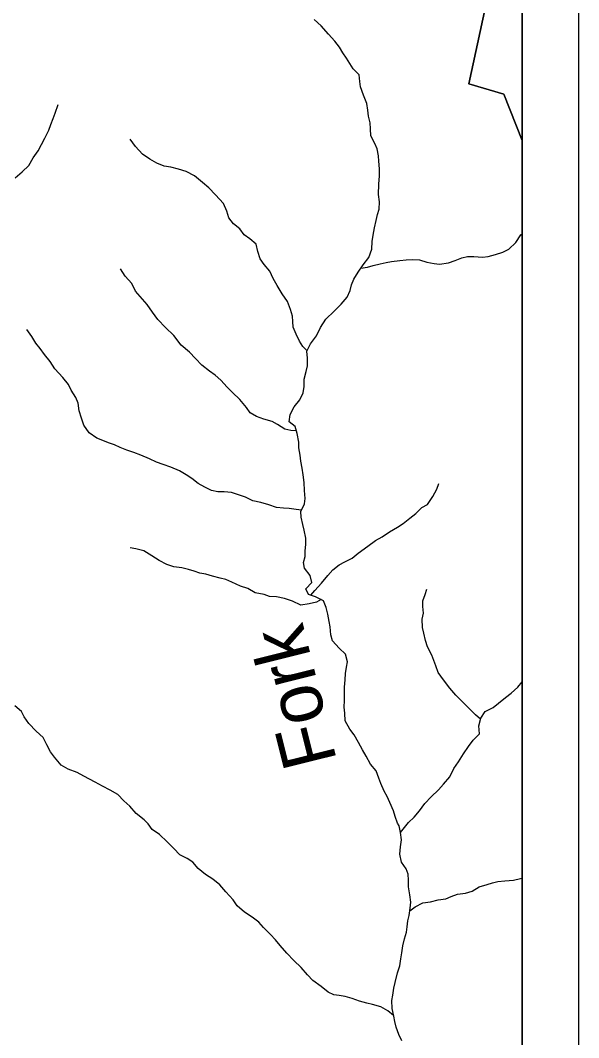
# Model space of a CAD drawing. Extents: x 0 to 34, y 0 to 22.
# Drawn here: x 8.014 to 9, y 17.355 to 19.152 of the extents above; entities that cross this region are included whole.
import ezdxf

# ---------------------------------------------------------------- set-up
doc = ezdxf.new("R2010")
doc.units = 0
for name, color, linetype in [('Default', 7, 'Continuous'), ('GM_X_Minor_River', 7, 'Continuous'), ('GM_X_Minor_River_Text', 7, 'Continuous'), ('SH_Cut_Line', 7, 'Continuous'), ('SH_Data', 7, 'Continuous')]:
    doc.layers.add(name, color=color, linetype=linetype)

msp = doc.modelspace()

# ---------------------------------------------------------------- linework, layer by layer
at = {"layer": 'Default'}
for points in [[(8.8461, 19.2253), (8.806, 19.0402), (8.8678, 19.0216), (8.9, 18.9397), (8.9, 20.9)], [(8.9, 14.1), (8.9, 18.9397), (8.8678, 19.0216), (8.806, 19.0402), (8.8461, 19.2253)]]:
    msp.add_lwpolyline(points, dxfattribs=at)
at = {"layer": 'GM_X_Minor_River'}
for points in [[(8.6401, 18.9346), (8.633, 18.948), (8.6327, 18.9605), (8.632, 18.9711), (8.6291, 18.9826), (8.6276, 18.9936), (8.6258, 19.0054), (8.6199, 19.0198), (8.6146, 19.0347), (8.6136, 19.0442), (8.6125, 19.056), (8.602, 19.0663), (8.59, 19.0854), (8.5836, 19.0949), (8.578, 19.1048), (8.5693, 19.1151), (8.5584, 19.1277), (8.5456, 19.1426), (8.5332, 19.1537)], [(8.0053, 18.8741), (8.0175, 18.8843), (8.029, 18.896), (8.0367, 18.9093), (8.0458, 18.9217), (8.0516, 18.9331), (8.0574, 18.9441), (8.0643, 18.9581), (8.0682, 18.9683), (8.0724, 18.9789), (8.0755, 18.9884), (8.0813, 19.0032)], [(8.5204, 18.5683), (8.513, 18.5761), (8.5074, 18.5856), (8.5014, 18.5978), (8.4958, 18.6104), (8.4955, 18.6199), (8.4948, 18.6294), (8.4914, 18.6416), (8.4862, 18.6553), (8.4765, 18.669), (8.4678, 18.6839), (8.4607, 18.6961), (8.4547, 18.7091), (8.4449, 18.7209), (8.4378, 18.7308), (8.4337, 18.7438), (8.4308, 18.7567), (8.4195, 18.7663), (8.4097, 18.7735), (8.4018, 18.7838), (8.3908, 18.7927), (8.3825, 18.803), (8.3788, 18.8148), (8.3729, 18.8285), (8.3586, 18.8438), (8.3473, 18.8564), (8.3356, 18.8659), (8.322, 18.8774), (8.3073, 18.8851), (8.2932, 18.889), (8.28, 18.8925), (8.2679, 18.8945), (8.255, 18.8999), (8.2426, 18.9072), (8.2297, 18.916), (8.2177, 18.9294), (8.2083, 18.9423)], [(8.6829, 17.7294), (8.6803, 17.7341), (8.6758, 17.7459), (8.6732, 17.7558), (8.6669, 17.7703), (8.662, 17.7809), (8.6568, 17.7904), (8.6508, 17.8038), (8.6471, 17.8137), (8.6422, 17.8262), (8.6324, 17.8381), (8.625, 17.8522), (8.6186, 17.8632), (8.6115, 17.8766), (8.6036, 17.8899), (8.5961, 17.8999), (8.5878, 17.9147), (8.5872, 17.928), (8.5861, 17.9387), (8.5866, 17.9504), (8.5867, 17.9744), (8.5876, 17.9873), (8.5884, 17.9983), (8.59, 18.0093), (8.5916, 18.0191), (8.5882, 18.0325), (8.5769, 18.0432), (8.5656, 18.0558), (8.5623, 18.0664), (8.5613, 18.0809), (8.5594, 18.0904), (8.5572, 18.1033), (8.5543, 18.1147), (8.5494, 18.1269), (8.5354, 18.1338), (8.5233, 18.1381), (8.5185, 18.1476), (8.5288, 18.1593), (8.5258, 18.1715), (8.5157, 18.1841), (8.5139, 18.1944), (8.5173, 18.205), (8.5174, 18.2145), (8.5182, 18.227), (8.5183, 18.2376), (8.5154, 18.2513), (8.5128, 18.2616), (8.5102, 18.2745), (8.5095, 18.2844), (8.5161, 18.2981), (8.5169, 18.3075), (8.5158, 18.3216), (8.5152, 18.336), (8.5138, 18.349), (8.5119, 18.3611), (8.5097, 18.3737), (8.5083, 18.3843), (8.5057, 18.3969), (8.5062, 18.4068), (8.5032, 18.422), (8.4992, 18.4345), (8.489, 18.4429), (8.4906, 18.4559), (8.4979, 18.4695), (8.5078, 18.4816), (8.5136, 18.4944), (8.5152, 18.5051), (8.5153, 18.518), (8.5191, 18.5316), (8.5211, 18.5419), (8.5212, 18.5552), (8.5201, 18.5677), (8.5267, 18.5806), (8.537, 18.5946), (8.5443, 18.6093), (8.5539, 18.6241), (8.5684, 18.6381), (8.5806, 18.6505), (8.5913, 18.6634), (8.5963, 18.6747), (8.599, 18.685), (8.6033, 18.6948), (8.6106, 18.7073), (8.6194, 18.7202), (8.6297, 18.733), (8.6347, 18.7482), (8.6352, 18.7615), (8.6372, 18.7725), (8.6395, 18.7854), (8.6423, 18.7986), (8.645, 18.8093), (8.6477, 18.8187), (8.6486, 18.8313), (8.6467, 18.8446), (8.6472, 18.8628), (8.6485, 18.8772), (8.6482, 18.8898), (8.6471, 18.9031), (8.6464, 18.9129), (8.6442, 18.9251), (8.6401, 18.9346)], [(8.6153, 18.7142), (8.6273, 18.7163), (8.6372, 18.7193), (8.6497, 18.7222), (8.66, 18.7241), (8.6698, 18.7263), (8.6843, 18.7277), (8.6956, 18.7288), (8.7063, 18.7299), (8.7188, 18.729), (8.732, 18.7251), (8.7449, 18.7224), (8.7544, 18.7216), (8.7703, 18.7237), (8.7821, 18.7278), (8.7935, 18.7327), (8.8038, 18.7349), (8.8148, 18.7352), (8.8303, 18.734), (8.8402, 18.7347), (8.8531, 18.7384), (8.8664, 18.7425), (8.8767, 18.7478), (8.8892, 18.7598), (8.8981, 18.7731), (8.9, 18.775)], [(8.5016, 18.4271), (8.4919, 18.4277), (8.4813, 18.4297), (8.4685, 18.4381), (8.4586, 18.4435), (8.4443, 18.4474), (8.4314, 18.4521), (8.4201, 18.459), (8.4133, 18.4685), (8.402, 18.4826), (8.3888, 18.4945), (8.3794, 18.504), (8.3685, 18.5166), (8.3583, 18.5255), (8.3485, 18.5324), (8.3349, 18.5431), (8.3233, 18.5549), (8.3127, 18.566), (8.298, 18.5786), (8.2852, 18.5954), (8.2705, 18.6096), (8.257, 18.6237), (8.2476, 18.6367), (8.2382, 18.65), (8.2258, 18.6642), (8.2175, 18.6737), (8.2108, 18.6871), (8.1991, 18.7004), (8.1912, 18.7134)], [(8.5107, 18.2869), (8.5012, 18.2883), (8.4887, 18.2899), (8.4789, 18.2903), (8.4667, 18.2915), (8.4531, 18.2962), (8.4391, 18.3004), (8.4247, 18.3036), (8.4119, 18.3101), (8.3979, 18.3144), (8.3873, 18.3183), (8.3744, 18.3195), (8.363, 18.3192), (8.352, 18.3215), (8.3399, 18.3273), (8.3282, 18.3342), (8.3169, 18.3426), (8.3071, 18.3492), (8.2954, 18.3564), (8.2799, 18.3626), (8.2663, 18.3676), (8.2545, 18.3719), (8.2421, 18.3777), (8.2269, 18.3839), (8.2148, 18.3889), (8.2023, 18.3931), (8.1902, 18.3974), (8.1804, 18.402), (8.1698, 18.4059), (8.16, 18.4097), (8.1494, 18.414), (8.1358, 18.4236), (8.1264, 18.4369), (8.1223, 18.4491), (8.1179, 18.4624), (8.1164, 18.4761), (8.112, 18.486), (8.1041, 18.499), (8.0992, 18.5089), (8.0894, 18.5215), (8.0751, 18.5368), (8.0669, 18.5494), (8.0571, 18.5619), (8.0492, 18.5723), (8.0417, 18.5818), (8.0346, 18.5936), (8.0255, 18.6058)], [(8.5274, 18.1367), (8.534, 18.1452), (8.5462, 18.1577), (8.5573, 18.1717), (8.5657, 18.1815), (8.5772, 18.1905), (8.5874, 18.1954), (8.6, 18.2022), (8.611, 18.2108), (8.6278, 18.2233), (8.6411, 18.2331), (8.6529, 18.2398), (8.6659, 18.2485), (8.68, 18.2571), (8.6899, 18.2631), (8.7021, 18.2729), (8.7124, 18.2808), (8.7234, 18.2914), (8.733, 18.297), (8.7425, 18.311), (8.7498, 18.3239), (8.7529, 18.3341)], [(8.5455, 18.1289), (8.5373, 18.1243), (8.524, 18.1214), (8.5092, 18.1188), (8.4948, 18.1261), (8.4804, 18.1308), (8.4664, 18.1335), (8.4543, 18.1344), (8.4445, 18.1378), (8.4289, 18.141), (8.4157, 18.1487), (8.4032, 18.1525), (8.3877, 18.1595), (8.3768, 18.1645), (8.3669, 18.1668), (8.3533, 18.1703), (8.3419, 18.1738), (8.3313, 18.1758), (8.3211, 18.1793), (8.3109, 18.182), (8.2992, 18.1847), (8.2855, 18.1867), (8.273, 18.191), (8.2594, 18.1979), (8.2462, 18.2063), (8.2323, 18.2152), (8.2182, 18.2183), (8.2084, 18.2206)], [(8.8267, 17.9178), (8.8181, 17.9254), (8.8068, 17.9365), (8.794, 17.9495), (8.7834, 17.9598), (8.7725, 17.9724), (8.7612, 17.9869), (8.7518, 18.0003), (8.7477, 18.0117), (8.7444, 18.0212), (8.7407, 18.0307), (8.7332, 18.0452), (8.7295, 18.0566), (8.7269, 18.0696), (8.7243, 18.0795), (8.724, 18.0943), (8.726, 18.1049), (8.7246, 18.1167), (8.725, 18.1269), (8.7292, 18.1379), (8.732, 18.1474)], [(8.6855, 17.7177), (8.6996, 17.7351), (8.7096, 17.7445), (8.7191, 17.7559), (8.7283, 17.7687), (8.7398, 17.7804), (8.7527, 17.7929), (8.7615, 17.8031), (8.7726, 17.8159), (8.7799, 17.8303), (8.7876, 17.8424), (8.7964, 17.8564), (8.8056, 17.8696), (8.8136, 17.8806), (8.8247, 17.8919), (8.8236, 17.9056), (8.8271, 17.9196), (8.8352, 17.931), (8.8489, 17.9381), (8.8584, 17.946), (8.8706, 17.9562), (8.8809, 17.9637), (8.8927, 17.9743), (8.9, 17.9834)], [(8.24, 17.7328), (8.2329, 17.7396), (8.2189, 17.7507), (8.2076, 17.7637), (8.1971, 17.7736), (8.1862, 17.7843), (8.1726, 17.792), (8.1593, 17.799), (8.1461, 17.8066), (8.1363, 17.8116), (8.1261, 17.817), (8.1147, 17.8235), (8.0985, 17.8294), (8.0864, 17.8366), (8.0747, 17.8504), (8.0676, 17.8599), (8.0612, 17.8725), (8.0545, 17.8851), (8.042, 17.8966), (8.0292, 17.9099), (8.021, 17.9218), (8.0161, 17.9313), (8.0044, 17.9412)], [(8.6732, 17.3942), (8.663, 17.4023), (8.6505, 17.4092), (8.636, 17.4135), (8.6262, 17.4158), (8.6133, 17.4193), (8.6, 17.4243), (8.5875, 17.4278), (8.5772, 17.4294), (8.5677, 17.4306), (8.5579, 17.4356), (8.5454, 17.4455), (8.5306, 17.4558), (8.5212, 17.4658), (8.5102, 17.4791), (8.497, 17.4914), (8.4849, 17.5043), (8.4732, 17.5181), (8.4649, 17.5276), (8.4559, 17.5372), (8.4438, 17.5494), (8.4355, 17.5589), (8.4234, 17.5681), (8.4101, 17.5769), (8.3969, 17.588), (8.3901, 17.5983), (8.3769, 17.6124), (8.3663, 17.625), (8.3542, 17.6349), (8.341, 17.6434), (8.3281, 17.6537), (8.3187, 17.6651), (8.3088, 17.6717), (8.296, 17.6778), (8.2854, 17.6893), (8.2737, 17.7011), (8.2597, 17.7141), (8.2472, 17.7225), (8.24, 17.7328)], [(8.6877, 17.3494), (8.6825, 17.3604), (8.678, 17.3734), (8.6754, 17.3833), (8.6735, 17.3928), (8.6706, 17.4068), (8.6699, 17.4205), (8.6719, 17.43), (8.6735, 17.4425), (8.6762, 17.4524), (8.6801, 17.4694), (8.684, 17.4819), (8.6863, 17.4945), (8.6879, 17.5047), (8.6895, 17.5172), (8.6926, 17.5294), (8.6958, 17.5411), (8.6973, 17.5506), (8.6985, 17.5612), (8.7005, 17.5707), (8.7025, 17.5836), (8.7037, 17.5946), (8.7019, 17.6075), (8.6993, 17.6216), (8.6994, 17.6334), (8.6987, 17.6436), (8.6953, 17.6531), (8.6874, 17.6653), (8.6845, 17.679), (8.6857, 17.6923), (8.6873, 17.7044), (8.6855, 17.7177), (8.6829, 17.7294)], [(8.7018, 17.579), (8.7116, 17.5862), (8.7246, 17.5933), (8.7383, 17.5952), (8.752, 17.5985), (8.7653, 17.6003), (8.7752, 17.6045), (8.7859, 17.6082), (8.8, 17.61), (8.8118, 17.6137), (8.8244, 17.6216), (8.8385, 17.6254), (8.848, 17.6283), (8.8575, 17.6306), (8.8697, 17.632), (8.8849, 17.6334), (8.8971, 17.6364), (8.9, 17.637)]]:
    msp.add_lwpolyline(points, dxfattribs=at)
at = {"layer": 'SH_Cut_Line'}
msp.add_lwpolyline([(2.4352, 14.1), (8.9, 14.1), (8.9, 20.9), (2.4845, 20.9), (2.4809, 20.6393), (2.4757, 20.2566), (2.4573, 18.9074), (2.4581, 18.1825), (2.4581, 18.1772), (2.4586, 17.7785), (2.4545, 17.2795), (2.4313, 15.0183), (2.4372, 14.2719)], close=True, dxfattribs=at)
at = {"layer": 'SH_Data'}
for p, q in [((9, 21), (9, 14)), ((8.9, 20.9), (8.9, 14.1))]:
    msp.add_line(p, q, dxfattribs=at)

# ---------------------------------------------------------------- texts
at = {"layer": 'GM_X_Minor_River_Text'}
msp.add_text('Fork', height=0.0947, rotation=104.0019, dxfattribs=at).set_placement((8.5736, 17.8439))

doc.saveas('drawing.dxf')
